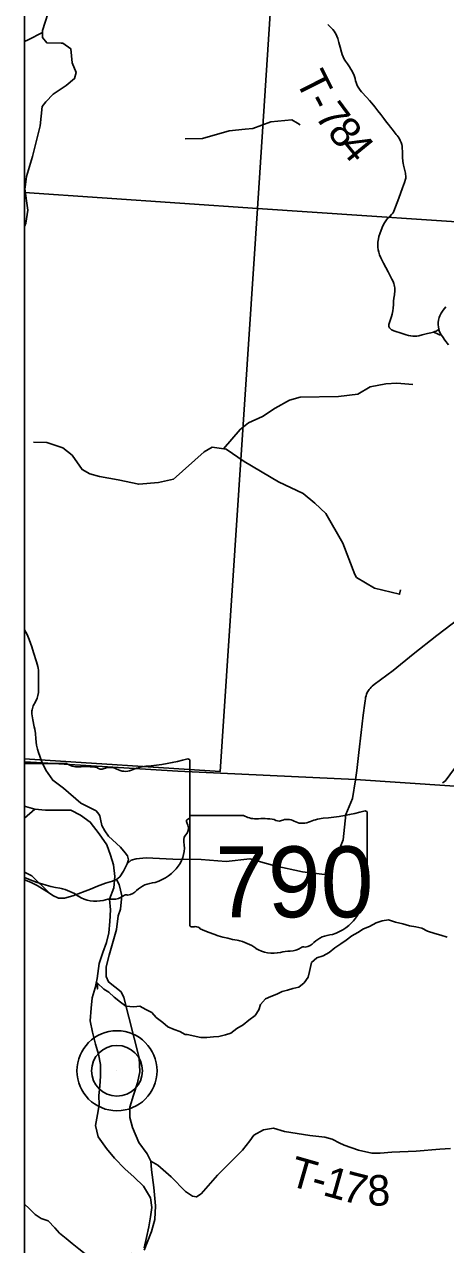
# Model space of a CAD drawing. Extents: x 396.2 to 468.4, y 232.6 to 279.1.
# Drawn here: x 413.851 to 414.633, y 269.775 to 272.044 of the extents above; entities that cross this region are included whole.
import ezdxf

# ---------------------------------------------------------------- set-up
doc = ezdxf.new("R2010")
doc.units = 0
for name, color, linetype in [('Default', 7, 'Continuous'), ('GM_X_County_Road', 7, 'Continuous'), ('GM_X_Minor_River', 7, 'Continuous'), ('GM_X_Section', 7, 'Continuous'), ('GM_X_State_Location', 7, 'Continuous'), ('GM_X_State_Route', 7, 'Continuous'), ('GM_X_State_Shield', 7, 'Continuous'), ('GM_X_Township_Road', 7, 'Continuous'), ('GM_X_Township_Road_Text', 7, 'Continuous'), ('GM_X_Unincorporated', 7, 'Continuous'), ('GM_X_Unincorporated_Location', 7, 'Continuous'), ('SH_Cut_Line', 7, 'Continuous'), ('TX_P_1', 7, 'Continuous')]:
    doc.layers.add(name, color=color, linetype=linetype)

msp = doc.modelspace()

# ---------------------------------------------------------------- linework, layer by layer
at = {"layer": 'Default'}
msp.add_lwpolyline([(413.8513, 276.7667), (413.8513, 270.6726), (413.8849, 270.6706), (414.1359, 270.6553), (414.466, 270.6401), (415.2492, 270.5871)], dxfattribs=at)
for points in [[(413.8513, 272.7988), (413.8513, 271.7315), (414.2837, 271.7015), (414.3535, 272.7693)], [(413.8513, 271.7315), (413.8513, 270.6782), (414.2148, 270.6549), (414.2837, 271.7015)], [(413.8513, 270.6726), (413.8513, 264.4868), (414.0592, 264.474), (414.3542, 264.4559), (414.8754, 264.4239), (414.9163, 265.108), (414.9927, 266.2714), (414.9935, 266.2891), (414.9982, 266.4735), (415.0293, 266.9964), (415.0582, 267.4588), (415.0934, 268.0402), (415.1765, 269.4523), (415.2459, 270.5284), (415.2492, 270.5871), (414.466, 270.6401), (414.1359, 270.6553), (413.8849, 270.6706)]]:
    msp.add_lwpolyline(points, close=True, dxfattribs=at)
at = {"layer": 'GM_X_County_Road'}
for points in [[(414.6387, 271.4482), (414.6318, 271.4569), (414.6274, 271.4633), (414.6251, 271.4668), (414.6243, 271.468), (414.622, 271.4722), (414.6205, 271.4766), (414.6203, 271.4776), (414.6197, 271.4812), (414.6193, 271.4858), (414.6195, 271.4897), (414.6202, 271.4941), (414.6215, 271.4989), (414.6226, 271.5023), (414.6247, 271.5067), (414.6286, 271.5128), (414.6333, 271.519)], [(414.0738, 269.7646), (414.0869, 269.7992), (414.0932, 269.822), (414.0945, 269.8475), (414.0913, 269.8812), (414.0873, 269.9139), (414.0861, 269.9302), (414.0792, 269.9442), (414.0639, 269.9651), (414.052, 269.9927), (414.047, 270.0113), (414.0472, 270.0307), (414.0536, 270.0527), (414.0614, 270.0756), (414.0658, 270.0961), (414.0642, 270.1227), (414.0358, 270.2346), (414.0309, 270.2448), (414.0191, 270.2546), (414.0076, 270.2637), (414.003, 270.2736), (414.0029, 270.2918), (414.0089, 270.3135), (414.0222, 270.361), (414.0251, 270.3865), (414.0294, 270.3988), (414.031, 270.412), (414.0323, 270.4238), (414.0269, 270.4448), (414.0221, 270.4539)]]:
    msp.add_lwpolyline(points, dxfattribs=at)
at = {"layer": 'GM_X_Minor_River'}
for p, q in [((413.8536, 271.7481), (413.8513, 271.7465)), ((413.8706, 270.5846), (413.8513, 270.5679))]:
    msp.add_line(p, q, dxfattribs=at)
for points in [[(413.9005, 272.0812), (413.8849, 272.0325), (413.8851, 272.0196), (413.8927, 272.0098), (413.9195, 272.0091), (413.9226, 272.0093), (413.9373, 271.9985), (413.9397, 271.9726), (413.9473, 271.9544), (413.9445, 271.9432), (413.9285, 271.9302), (413.9047, 271.9141), (413.8909, 271.8999), (413.8841, 271.8911), (413.8807, 271.8552), (413.8663, 271.7981), (413.8553, 271.761), (413.8527, 271.7414), (413.8522, 271.7384), (413.8574, 271.6987), (413.8541, 271.6746), (413.8513, 271.6679)], [(413.8849, 272.0286), (413.8584, 272.0153), (413.8513, 272.0119)], [(414.1499, 271.8314), (414.1821, 271.8316), (414.2313, 271.8459), (414.2608, 271.8488), (414.2753, 271.8502), (414.3089, 271.8625), (414.3476, 271.8662), (414.3583, 271.8601), (414.3631, 271.8572)], [(414.2211, 271.2549), (414.2516, 271.2907), (414.2671, 271.3032), (414.2935, 271.3148), (414.317, 271.3304), (414.3432, 271.3455), (414.3634, 271.3506), (414.4345, 271.3521), (414.4701, 271.3563), (414.4932, 271.37), (414.5221, 271.3755), (414.5429, 271.3771), (414.5723, 271.3743)], [(414.1279, 271.1982), (414.1001, 271.1921), (414.0634, 271.1889), (414.0255, 271.1968), (413.9906, 271.2033), (413.9727, 271.2084), (413.9584, 271.2162), (413.9396, 271.243), (413.9227, 271.2564), (413.8929, 271.2664), (413.8679, 271.267)], [(414.1272, 271.198), (414.1849, 271.2492), (414.1999, 271.2578), (414.2255, 271.2543), (414.2592, 271.2309), (414.3227, 271.1935), (414.3689, 271.1719), (414.3907, 271.1537), (414.4109, 271.1345), (414.4421, 271.0792), (414.4649, 271.0211), (414.4678, 271.0157), (414.5012, 270.9956), (414.5477, 270.9843), (414.5495, 270.9926)], [(414.6271, 270.6338), (414.6321, 270.6371), (414.6967, 270.7243), (414.7116, 270.7413), (414.7267, 270.7529), (414.7577, 270.7649), (414.7833, 270.7618), (414.7992, 270.7628), (414.82, 270.775), (414.8393, 270.8017)], [(413.9971, 270.318), (414.0039, 270.3369), (414.0078, 270.3551), (414.0101, 270.3756), (414.0109, 270.3976), (414.0094, 270.4173), (414.017, 270.4385), (414.0194, 270.4598), (414.0164, 270.481), (414.0111, 270.4992), (414.0044, 270.5182), (413.99, 270.5388), (413.9734, 270.5608), (413.9553, 270.5737), (413.9372, 270.5829), (413.8902, 270.583), (413.8706, 270.5846), (413.8532, 270.5899), (413.8513, 270.5911)], [(414.1532, 270.1655), (414.1787, 270.1602), (414.1901, 270.1602), (414.2022, 270.1613), (414.2124, 270.1621), (414.2245, 270.1651), (414.2343, 270.1685), (414.2453, 270.1772), (414.2574, 270.184), (414.2677, 270.1927), (414.2798, 270.2014), (414.2862, 270.2116), (414.2897, 270.2215), (414.2988, 270.2321), (414.3086, 270.2366), (414.3196, 270.2408), (414.3298, 270.2457), (414.3396, 270.2479), (414.3495, 270.251), (414.3605, 270.254), (414.3703, 270.2619), (414.3783, 270.2721), (414.3806, 270.2831), (414.384, 270.2994), (414.3942, 270.3085), (414.406, 270.3123), (414.4173, 270.318), (414.4275, 270.327), (414.4389, 270.3346), (414.4488, 270.3414), (414.459, 270.349), (414.4703, 270.3554), (414.4809, 270.3622), (414.4919, 270.3668), (414.5044, 270.3736), (414.5154, 270.3773), (414.5271, 270.3792), (414.5404, 270.3746), (414.554, 270.3716), (414.5661, 270.3678), (414.5778, 270.3659), (414.5891, 270.3632), (414.5994, 270.3579), (414.613, 270.3537), (414.6243, 270.3506), (414.636, 270.3468)], [(414.0737, 269.7693), (414.0782, 269.7882), (414.0821, 269.808), (414.0852, 269.8269), (414.0875, 269.8444), (414.0852, 269.8618), (414.0724, 269.8838), (414.0551, 269.9006), (414.0377, 269.9158), (414.0188, 269.9356), (414.0037, 269.9538), (413.9879, 269.9758), (413.9834, 269.9963), (413.9872, 270.0168), (413.9903, 270.035), (413.9896, 270.0525), (413.9912, 270.0699), (413.9927, 270.0881), (413.9928, 270.1101), (413.989, 270.1291), (413.983, 270.1481), (413.9778, 270.1701), (413.9733, 270.1913), (413.9749, 270.2148), (413.9772, 270.2338), (413.9825, 270.2528), (413.9864, 270.2702), (413.9902, 270.2975), (413.9971, 270.318)], [(413.9846, 270.2622), (413.9868, 270.2504), (413.9872, 270.2614), (413.9985, 270.25), (414.008, 270.2443), (414.0179, 270.2349), (414.0296, 270.2258), (414.0395, 270.2182), (414.0546, 270.2171), (414.0653, 270.2182), (414.0766, 270.2121), (414.0876, 270.2068), (414.096, 270.1974), (414.1081, 270.1883), (414.1176, 270.1803), (414.1293, 270.175), (414.1399, 270.1712), (414.1494, 270.1655), (414.1532, 270.1655)], [(414.0679, 269.7558), (414.05, 269.7588), (414.0359, 269.7576), (414.0246, 269.7569), (414.0132, 269.7534), (414.0026, 269.7519), (413.9894, 269.7542), (413.9754, 269.7557), (413.964, 269.758), (413.9522, 269.7671), (413.9401, 269.7769), (413.9287, 269.7864), (413.9166, 269.7966), (413.9079, 269.8065), (413.8954, 269.8194), (413.8825, 269.8239), (413.8715, 269.8311), (413.8601, 269.8425), (413.8513, 269.8503)]]:
    msp.add_lwpolyline(points, dxfattribs=at)
at = {"layer": 'GM_X_Section'}
msp.add_lwpolyline([(414.3535, 272.7693), (415.3883, 272.7052), (415.3792, 272.5676), (415.3171, 271.632), (414.2837, 271.7015)], close=True, dxfattribs=at)
at = {"layer": 'GM_X_State_Route'}
for points in [[(414.4662, 270.6395), (414.4684, 270.6567), (414.4722, 270.6899), (414.4764, 270.7276), (414.4803, 270.7597), (414.483, 270.7819), (414.4836, 270.7863), (414.4842, 270.7898), (414.4847, 270.7926), (414.4854, 270.7954), (414.4864, 270.7983), (414.4877, 270.8014), (414.4888, 270.8035), (414.4901, 270.8056), (414.4915, 270.8073), (414.4931, 270.8094), (414.495, 270.8113), (414.4971, 270.8132), (414.5008, 270.8164), (414.5356, 270.8426), (414.5728, 270.8728), (414.6171, 270.9076), (414.6713, 270.9492)], [(413.8851, 270.67), (413.8838, 270.673), (413.8799, 270.683), (413.8772, 270.69), (413.8753, 270.6963), (413.8739, 270.7035), (413.8727, 270.7153), (413.8717, 270.7254), (413.8704, 270.7336), (413.8694, 270.738), (413.8666, 270.7509), (413.8654, 270.7581), (413.865, 270.7619), (413.865, 270.7648), (413.8651, 270.7673), (413.8654, 270.7697), (413.8662, 270.7722), (413.8677, 270.7766), (413.8717, 270.7845), (413.8747, 270.791), (413.8764, 270.7962), (413.8771, 270.8019), (413.8774, 270.8085), (413.8775, 270.8266), (413.8775, 270.8335), (413.8771, 270.8429), (413.8767, 270.8467), (413.8761, 270.8498), (413.8751, 270.8542), (413.8739, 270.8585), (413.8683, 270.8759), (413.8649, 270.8864), (413.8602, 270.9004), (413.8565, 270.9094), (413.8517, 270.9184), (413.8513, 270.919)], [(414.042, 270.4829), (414.0443, 270.4908), (414.0425, 270.498), (414.0381, 270.5037), (414.0295, 270.5144), (414.0074, 270.5347), (414.0003, 270.5443), (413.9952, 270.5542), (413.9923, 270.5664), (413.9913, 270.5721), (413.9894, 270.5756), (413.9846, 270.5814), (413.977, 270.5853), (413.9563, 270.5962), (413.9238, 270.6235), (413.904, 270.6386), (413.8912, 270.6574), (413.8851, 270.67)], [(414.042, 270.4829), (414.0493, 270.4897), (414.0586, 270.4922), (414.077, 270.4942), (414.1269, 270.4917), (414.1791, 270.4911), (414.2257, 270.4876), (414.2697, 270.4927), (414.316, 270.4793), (414.3677, 270.4682), (414.4139, 270.4627), (414.4312, 270.4978), (414.4432, 270.5278), (414.4478, 270.575), (414.4602, 270.6043), (414.4662, 270.6395)], [(413.8513, 270.4525), (413.8531, 270.4527), (413.864, 270.4487), (413.8749, 270.4429), (413.8978, 270.4283), (413.9042, 270.4242), (413.9147, 270.4195), (413.9257, 270.4193), (413.9413, 270.4233), (413.9737, 270.4361), (413.9871, 270.4416), (414.0016, 270.4474), (414.0145, 270.4507), (414.0221, 270.4539), (414.0281, 270.4587), (414.035, 270.4694), (414.042, 270.4829)]]:
    msp.add_lwpolyline(points, dxfattribs=at)
at = {"layer": 'GM_X_State_Shield'}
for p, q in [((414.2579, 270.5731), (414.1614, 270.5731)), ((414.4878, 270.4734), (414.4878, 270.5781)), ((414.1582, 270.5697), (414.1582, 270.3696)), ((414.4877, 270.4734), (414.4878, 270.4734))]:
    msp.add_line(p, q, dxfattribs=at)
for points in [[(413.9288, 270.6698), (413.8513, 270.6698), (413.8513, 270.4577)], [(414.1586, 270.5701), (414.1586, 270.5701), (414.1586, 270.5701), (414.1586, 270.675)]]:
    msp.add_lwpolyline(points, dxfattribs=at)
for centre, major_axis, start_param, end_param in [((413.9518, 270.693), (0.037, 0), 4.042888, 4.731792), ((413.964, 270.5575), (0.133, 0), 1.404758, 1.657859), ((414.0858, 270.6087), (0.0703, 0), 1.699012, 2.107814), ((414.0412, 270.9426), (0.3495, 0), 4.814394, 5.042369), ((414.1549, 270.6752), (0.00367, 0), 6.197627, 7.989034), ((413.9942, 270.6678), (0.0107, 0), 3.836095, 5.185415), ((414.0099, 270.6447), (0.0222, 0), 0.950623, 2.079405), ((414.0386, 270.6764), (0.0267, 0), 4.08156, 5.145723), ((414.1619, 270.5701), (0.00382, 0), 1.712693, 3.28349), ((414.2809, 270.5964), (0.037, 0), 4.042523, 4.731795), ((414.3703, 270.846), (0.3495, 0), 4.814394, 5.042369), ((414.4841, 270.5785), (0.00367, 0), 6.141152, 7.989035), ((414.1577, 270.5624), (0.00568, 0), 1.883978, 3.671073), ((414.1216, 270.5492), (0.0341, 0), 5.934695, 6.695948), ((414.1547, 270.5697), (0.00393, 0), 5.05454, 6.418171), ((414.2932, 270.4608), (0.133, 0), 1.404758, 1.657858), ((414.3234, 270.5712), (0.0107, 0), 3.836095, 5.185415), ((414.3391, 270.548), (0.0222, 0), 0.950623, 2.079405), ((414.3677, 270.5798), (0.0267, 0), 4.081561, 5.145723), ((414.4149, 270.512), (0.0703, 0), 1.699011, 2.107814), ((414.1717, 270.5263), (0.0248, 0), 2.387724, 3.262537), ((414.0608, 270.513), (0.0874, 0), 5.101753, 6.440018), ((414.4869, 270.4657), (0.00568, 0), 1.883978, 3.671073), ((414.4508, 270.4525), (0.0341, 0), 5.934695, 6.695948), ((414.4838, 270.473), (0.00393, 0), 5.05454, 6.418171), ((413.9732, 270.6345), (0.2524, 0), 4.208232, 4.488961), ((413.898, 270.3763), (0.079, 0), 0.823519, 1.323587), ((414.0976, 270.4101), (0.0479, 0), 1.647645, 2.488434), ((414.5009, 270.4296), (0.0248, 0), 2.387724, 3.262537), ((413.9834, 270.4537), (0.0501, 0), 4.026481, 4.996735), ((414.0124, 270.3845), (0.0412, 0), 1.495662, 1.94098), ((414.016, 270.4387), (0.0267, 0), 4.691044, 5.507374), ((414.0402, 270.4193), (0.00752, 0), 1.147584, 2.315152), ((414.037, 270.4468), (0.0282, 0), 4.937069, 5.64225), ((414.3899, 270.4163), (0.0874, 0), 5.101752, 6.440018), ((414.162, 270.3691), (0.00385, 0), 3.00124, 4.508301), ((414.1626, 270.3896), (0.0294, 0), 4.665946, 4.897461), ((414.1686, 270.358), (0.0106, 0), 0.519207, 1.627899), ((414.3024, 270.5378), (0.2524, 0), 4.195997, 4.488961), ((414.4268, 270.3134), (0.0479, 0), 1.647645, 2.488434), ((414.2272, 270.2797), (0.079, 0), 0.823519, 1.323587), ((414.3126, 270.357), (0.0501, 0), 4.026481, 4.996735), ((414.3452, 270.3421), (0.0267, 0), 4.691044, 5.507374), ((414.3693, 270.3227), (0.00752, 0), 1.147584, 2.315152), ((414.3661, 270.3502), (0.0282, 0), 4.937069, 5.64225), ((414.3415, 270.2878), (0.0412, 0), 1.495662, 1.94098)]:
    msp.add_ellipse(centre, major_axis=major_axis, ratio=0.8, start_param=start_param, end_param=end_param, dxfattribs=at)
at = {"layer": 'GM_X_Township_Road'}
for points in [[(414.6205, 271.4766), (414.6177, 271.475), (414.6156, 271.4738), (414.6133, 271.4727), (414.6105, 271.4718), (414.6056, 271.4703), (414.5997, 271.4689), (414.5897, 271.4664), (414.5833, 271.465), (414.5795, 271.4644), (414.5758, 271.4641), (414.5724, 271.4642), (414.5684, 271.4647), (414.5643, 271.4654), (414.5601, 271.4666), (414.5523, 271.469), (414.537, 271.4742), (414.5346, 271.4752), (414.5327, 271.4763), (414.5312, 271.4773), (414.53, 271.4784), (414.529, 271.4796), (414.5284, 271.4809), (414.5279, 271.4823), (414.5278, 271.484), (414.5279, 271.4858), (414.5283, 271.4876), (414.5296, 271.4915), (414.533, 271.501), (414.5341, 271.505), (414.5348, 271.5083), (414.5352, 271.5111), (414.5358, 271.5162), (414.5363, 271.5229), (414.5367, 271.529), (414.5373, 271.5351), (414.538, 271.5412), (414.5388, 271.5489), (414.5389, 271.5516), (414.5389, 271.5542), (414.5386, 271.5568), (414.5378, 271.5595), (414.5369, 271.5624), (414.5356, 271.5658), (414.5336, 271.57), (414.531, 271.575), (414.5263, 271.5841), (414.5179, 271.6002), (414.5129, 271.61), (414.5105, 271.6153), (414.509, 271.6202), (414.5081, 271.6245), (414.5074, 271.6294), (414.5072, 271.6344), (414.5075, 271.6389), (414.5078, 271.6421), (414.5083, 271.6453), (414.5092, 271.6495), (414.5108, 271.6548), (414.5133, 271.6612), (414.5168, 271.6692), (414.5199, 271.6752), (414.5222, 271.6789), (414.5249, 271.6823), (414.5289, 271.6863), (414.5328, 271.6902), (414.5347, 271.6924), (414.5362, 271.6947), (414.5373, 271.6969), (414.5384, 271.6996), (414.5401, 271.7044), (414.5463, 271.7211), (414.5533, 271.7401), (414.557, 271.7501), (414.5588, 271.7562), (414.5591, 271.7582), (414.5593, 271.7603), (414.5593, 271.7626), (414.559, 271.765), (414.5586, 271.7675), (414.5581, 271.7697), (414.5549, 271.7823), (414.5542, 271.7857), (414.5537, 271.7887), (414.5535, 271.7915), (414.5533, 271.7948), (414.5531, 271.8024), (414.5529, 271.8071), (414.5527, 271.8145), (414.5524, 271.8177), (414.5519, 271.8207), (414.5508, 271.8243), (414.5491, 271.8283), (414.5469, 271.8321), (414.5448, 271.8351), (414.5433, 271.8371), (414.5415, 271.8395), (414.5376, 271.8444), (414.5337, 271.8492), (414.5306, 271.853), (414.5269, 271.8579), (414.5235, 271.8624), (414.5186, 271.8687), (414.5131, 271.8761), (414.5076, 271.8835), (414.5018, 271.8907), (414.496, 271.8977), (414.4919, 271.9024), (414.4869, 271.9077), (414.4772, 271.9184), (414.4745, 271.9217), (414.4719, 271.9252), (414.4698, 271.929), (414.4683, 271.9324), (414.4672, 271.9358), (414.4662, 271.9391), (414.465, 271.9432), (414.4639, 271.9469), (414.4625, 271.9507), (414.461, 271.9539), (414.4595, 271.9568), (414.4574, 271.9606), (414.4547, 271.9647), (414.4509, 271.9704), (414.4473, 271.9758), (414.4451, 271.9794), (414.4431, 271.9837), (414.4411, 271.9882), (414.4396, 271.9924), (414.4372, 272.0014), (414.4351, 272.0104), (414.433, 272.0176), (414.4313, 272.0222), (414.43, 272.0254), (414.4283, 272.0283), (414.4264, 272.0313), (414.4239, 272.0343), (414.4206, 272.0377), (414.4144, 272.0439)], [(414.6105, 271.4718), (414.6166, 271.469), (414.622, 271.4669), (414.6228, 271.4668), (414.6235, 271.4668), (414.6251, 271.4668)], [(413.8513, 270.4675), (413.8648, 270.4605), (413.8978, 270.4283)], [(414.0861, 269.9302), (414.0992, 269.9231), (414.124, 269.9013), (414.1502, 269.8737), (414.1632, 269.8654), (414.1707, 269.8639), (414.1791, 269.8697), (414.2096, 269.904), (414.236, 269.93), (414.2564, 269.9506), (414.2695, 269.9681), (414.2774, 269.9784), (414.2948, 269.9888), (414.3138, 269.9919), (414.3343, 269.9856), (414.3813, 269.9779), (414.409, 269.975), (414.4227, 269.9709), (414.4236, 269.9705), (414.4358, 269.9646)], [(414.4358, 269.9646), (414.4451, 269.9601), (414.4717, 269.9507), (414.496, 269.9452), (414.5115, 269.9453), (414.5331, 269.9473), (414.5786, 269.9491), (414.6222, 269.9524), (414.6423, 269.954)]]:
    msp.add_lwpolyline(points, dxfattribs=at)
at = {"layer": 'GM_X_Unincorporated'}
for radius in [0.0744, 0.0472]:
    msp.add_circle((414.0231, 270.0983), radius, dxfattribs=at)
at = {"layer": 'GM_X_Unincorporated_Location'}
msp.add_line((414.0231, 270.0983), (414.0231, 270.0983), dxfattribs=at)
at = {"layer": 'SH_Cut_Line'}
msp.add_lwpolyline([(413.8513, 277.8582), (413.8513, 270.6726), (413.8849, 270.6706), (414.1359, 270.6553), (414.466, 270.6401), (415.2492, 270.5871), (415.2459, 270.5284), (415.1765, 269.4523), (415.0934, 268.0402), (415.0582, 267.4588), (415.0293, 266.9964)], dxfattribs=at)
msp.add_lwpolyline([(413.8513, 270.6726), (413.8513, 264.2582), (416.1109, 264.2582), (415.3533, 264.289), (414.8684, 264.3083), (414.8754, 264.4239), (414.9163, 265.108), (414.9927, 266.2714), (414.9935, 266.2891), (414.9982, 266.4735), (415.0293, 266.9964), (415.0582, 267.4588), (415.0934, 268.0402), (415.1765, 269.4523), (415.2459, 270.5284), (415.2492, 270.5871), (414.466, 270.6401), (414.1359, 270.6553), (413.8849, 270.6706)], close=True, dxfattribs=at)
at = {"layer": 'TX_P_1'}
msp.add_line((413.8513, 277.8582), (413.8513, 264.2582), dxfattribs=at)

# ---------------------------------------------------------------- texts
at = {"layer": 'GM_X_State_Location'}
for s, p in [('s', (413.9901, 270.553)), ('r', (413.9901, 270.553)), ('s', (414.3193, 270.4563)), ('r', (414.3192, 270.4563))]:
    msp.add_text(s, height=0.000189, dxfattribs=at).set_placement(p)
for s, p in [('775', (413.9232, 270.5392)), ('790', (414.2524, 270.4426))]:
    msp.add_text(s, height=0.000189, rotation=0, dxfattribs=at).set_placement(p)
at = {"layer": 'GM_X_State_Shield'}
msp.add_text('790', height=0.13184, dxfattribs=at).set_placement((414.2051, 270.3837))
at = {"layer": 'GM_X_Township_Road_Text'}
for s, rotation, p in [('T', 296.6369, (414.3535, 271.9406)), ('-', 297.4903, (414.373, 271.9018)), ('7', 306.4206, (414.3888, 271.873)), ('8', 309.3317, (414.4116, 271.8423)), ('4', 309.3128, (414.4337, 271.8152)), ('T', 344.0581, (414.3395, 269.8858)), ('1', 344.2854, (414.403, 269.8677)), ('-', 344.104, (414.3804, 269.8741)), ('7', 345.6581, (414.4381, 269.8578)), ('8', 1.0738, (414.4886, 269.8472))]:
    msp.add_text(s, height=0.0568, rotation=rotation, dxfattribs=at).set_placement(p)

doc.saveas('drawing.dxf')
